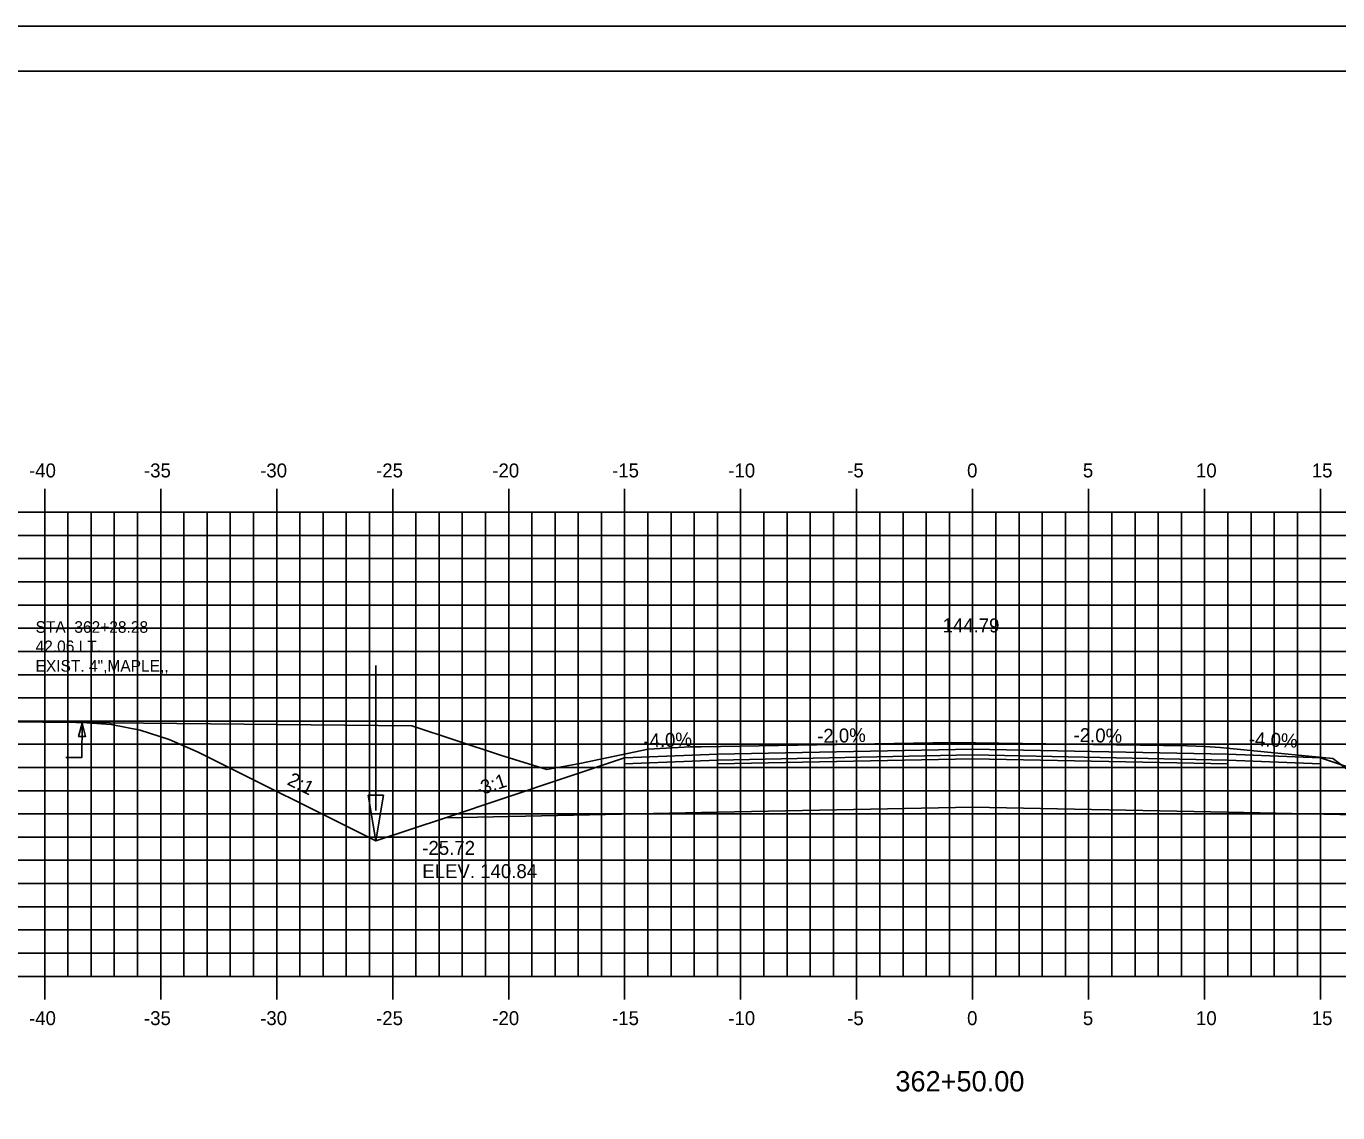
# Model space of a CAD drawing. Extents: x 1146746 to 1146916, y 608981 to 609091.
# Drawn here: x 1146788.6 to 1146845.2, y 609044.5 to 609091.3 of the extents above; entities that cross this region are included whole.
import ezdxf

# ---------------------------------------------------------------- set-up
doc = ezdxf.new("R2010")
doc.units = 0
for name, color, linetype in [('ANNOTATION', 7, 'Continuous'), ('BORDER', 7, 'Continuous'), ('D_Drainage_Ditch_Line', 7, 'Continuous'), ('D_Roadway_Centerline', 7, 'Continuous'), ('D_Roadway_Centerline_Text', 7, 'Continuous'), ('D_Roadway_Edge_Shoulder', 7, 'Continuous'), ('D_Roadway_Edge_TW', 7, 'Continuous'), ('D_Roadway_Pavement', 7, 'Continuous'), ('D_Roadway_SlopeLines', 7, 'Continuous'), ('D_Roadway_SubGrade', 7, 'Continuous'), ('D_Text_Monospaced', 7, 'Continuous'), ('D_Text_Standard', 7, 'Continuous'), ('H_V ANNOTATION', 7, 'Continuous'), ('MAJOR', 7, 'Continuous'), ('MINOR', 7, 'Continuous'), ('PLOT BOUNDARY', 7, 'Continuous'), ('S_Roadway_Centerline', 7, 'Continuous')]:
    doc.layers.add(name, color=color, linetype=linetype)

msp = doc.modelspace()

# ---------------------------------------------------------------- linework, layer by layer
msp.add_lwpolyline([(1146791.047, 609061.273), (1146792.297, 609061.185), (1146793.547, 609060.943), (1146794.797, 609060.547), (1146796.047, 609059.999), (1146803.703, 609056.171), (1146806.703, 609057.171), (1146814.427, 609059.745), (1146814.428, 609059.745), (1146818.428, 609059.905), (1146829.428, 609060.125), (1146840.428, 609059.905), (1146844.428, 609059.745), (1146852.151, 609057.171), (1146855.151, 609056.171), (1146862.242, 609059.716), (1146863.492, 609060.262), (1146864.742, 609060.648), (1146865.992, 609060.875), (1146867.242, 609060.943)])
at = {"layer": 'BORDER'}
msp.add_lwpolyline([(1146754.428, 608984.335), (1146914.428, 608984.335), (1146914.428, 609089.335), (1146754.428, 609089.335)], close=True, dxfattribs=at)
at = {"layer": 'D_Drainage_Ditch_Line'}
msp.add_line((1146803.703, 609057.483), (1146803.704, 609063.727), dxfattribs=at)
msp.add_lwpolyline([(1146803.375, 609058.139), (1146804.031, 609058.139), (1146803.703, 609056.171)], close=True, dxfattribs=at)
at = {"layer": 'D_Roadway_Edge_Shoulder'}
for points in [[(1146818.428, 609059.905), (1146814.428, 609059.745), (1146814.428, 609059.495), (1146818.428, 609059.655)], [(1146840.428, 609059.905), (1146844.428, 609059.745), (1146844.428, 609059.495), (1146840.428, 609059.655)]]:
    msp.add_lwpolyline(points, close=True, dxfattribs=at)
at = {"layer": 'D_Roadway_Edge_TW'}
msp.add_lwpolyline([(1146818.428, 609059.655), (1146818.428, 609059.905), (1146829.428, 609060.125), (1146840.428, 609059.905), (1146840.428, 609059.655), (1146829.428, 609059.875)], close=True, dxfattribs=at)
at = {"layer": 'D_Roadway_Pavement'}
msp.add_lwpolyline([(1146818.428, 609059.489), (1146818.428, 609059.655), (1146829.428, 609059.875), (1146840.428, 609059.655), (1146840.428, 609059.489), (1146829.428, 609059.709)], close=True, dxfattribs=at)
at = {"layer": 'D_Roadway_SlopeLines'}
for points in [[(1146803.703, 609056.171), (1146796.047, 609059.999), (1146794.797, 609060.547), (1146793.547, 609060.943), (1146792.297, 609061.185), (1146791.047, 609061.273)], [(1146806.703, 609057.171), (1146803.703, 609056.171)]]:
    msp.add_lwpolyline(points, dxfattribs=at)
at = {"layer": 'D_Roadway_SubGrade'}
for points in [[(1146818.428, 609059.489), (1146818.428, 609059.655), (1146814.428, 609059.495), (1146814.428, 609059.745), (1146814.427, 609059.745), (1146806.703, 609057.171), (1146818.428, 609057.405)], [(1146818.428, 609057.405), (1146818.428, 609059.489), (1146829.428, 609059.709), (1146840.428, 609059.489), (1146840.428, 609057.405), (1146829.428, 609057.625)], [(1146840.428, 609059.489), (1146840.428, 609059.655), (1146844.428, 609059.495), (1146844.428, 609059.745), (1146844.428, 609059.745), (1146852.151, 609057.171), (1146840.428, 609057.405)]]:
    msp.add_lwpolyline(points, close=True, dxfattribs=at)
at = {"layer": 'D_Text_Standard'}
msp.add_lwpolyline([(1146791.047, 609061.249), (1146791.023, 609059.762), (1146790.343, 609059.762)], dxfattribs=at)
msp.add_lwpolyline([(1146791.047, 609061.249), (1146791.183, 609060.665), (1146790.892, 609060.669)], close=True, dxfattribs=at)
at = {"layer": 'MAJOR'}
for p, q in [((1146789.428, 609071.337), (1146789.428, 609070.335)), ((1146794.428, 609071.337), (1146794.428, 609070.335)), ((1146799.428, 609071.337), (1146799.428, 609070.335)), ((1146804.428, 609071.337), (1146804.428, 609070.335)), ((1146809.428, 609071.337), (1146809.428, 609070.335)), ((1146814.428, 609071.337), (1146814.428, 609070.335)), ((1146819.428, 609071.337), (1146819.428, 609070.335)), ((1146824.428, 609071.337), (1146824.428, 609070.335)), ((1146829.428, 609071.337), (1146829.428, 609070.335)), ((1146834.428, 609071.337), (1146834.428, 609070.335)), ((1146839.428, 609071.337), (1146839.428, 609070.335)), ((1146844.428, 609071.337), (1146844.428, 609070.335)), ((1146759.428, 609070.335), (1146899.428, 609070.335)), ((1146759.428, 609070.335), (1146899.428, 609070.335)), ((1146789.428, 609050.335), (1146789.428, 609070.335)), ((1146794.428, 609050.335), (1146794.428, 609070.335)), ((1146799.428, 609050.335), (1146799.428, 609070.335)), ((1146804.428, 609050.335), (1146804.428, 609070.335)), ((1146809.428, 609050.335), (1146809.428, 609070.335)), ((1146814.428, 609050.335), (1146814.428, 609070.335)), ((1146819.428, 609050.335), (1146819.428, 609070.335)), ((1146824.428, 609050.335), (1146824.428, 609070.335)), ((1146829.428, 609050.335), (1146829.428, 609070.335)), ((1146834.428, 609050.335), (1146834.428, 609070.335)), ((1146839.428, 609050.335), (1146839.428, 609070.335)), ((1146844.428, 609050.335), (1146844.428, 609070.335)), ((1146759.428, 609065.335), (1146899.428, 609065.335)), ((1146759.428, 609060.335), (1146899.428, 609060.335)), ((1146759.428, 609055.335), (1146899.428, 609055.335)), ((1146759.428, 609050.335), (1146899.428, 609050.335)), ((1146759.428, 609050.335), (1146899.428, 609050.335)), ((1146789.428, 609049.333), (1146789.428, 609050.335)), ((1146794.428, 609049.333), (1146794.428, 609050.335)), ((1146799.428, 609049.333), (1146799.428, 609050.335)), ((1146804.428, 609049.333), (1146804.428, 609050.335)), ((1146809.428, 609049.333), (1146809.428, 609050.335)), ((1146814.428, 609049.333), (1146814.428, 609050.335)), ((1146819.428, 609049.333), (1146819.428, 609050.335)), ((1146824.428, 609049.333), (1146824.428, 609050.335)), ((1146829.428, 609049.333), (1146829.428, 609050.335)), ((1146834.428, 609049.333), (1146834.428, 609050.335)), ((1146839.428, 609049.333), (1146839.428, 609050.335)), ((1146844.428, 609049.333), (1146844.428, 609050.335))]:
    msp.add_line(p, q, dxfattribs=at)
at = {"layer": 'MINOR'}
for p, q in [((1146790.428, 609050.335), (1146790.428, 609070.335)), ((1146791.428, 609050.335), (1146791.428, 609070.335)), ((1146792.428, 609050.335), (1146792.428, 609070.335)), ((1146793.428, 609050.335), (1146793.428, 609070.335)), ((1146795.428, 609050.335), (1146795.428, 609070.335)), ((1146796.428, 609050.335), (1146796.428, 609070.335)), ((1146797.428, 609050.335), (1146797.428, 609070.335)), ((1146798.428, 609050.335), (1146798.428, 609070.335)), ((1146800.428, 609050.335), (1146800.428, 609070.335)), ((1146801.428, 609050.335), (1146801.428, 609070.335)), ((1146802.428, 609050.335), (1146802.428, 609070.335)), ((1146803.428, 609050.335), (1146803.428, 609070.335)), ((1146805.428, 609050.335), (1146805.428, 609070.335)), ((1146806.428, 609050.335), (1146806.428, 609070.335)), ((1146807.428, 609050.335), (1146807.428, 609070.335)), ((1146808.428, 609050.335), (1146808.428, 609070.335)), ((1146810.428, 609050.335), (1146810.428, 609070.335)), ((1146811.428, 609050.335), (1146811.428, 609070.335)), ((1146812.428, 609050.335), (1146812.428, 609070.335)), ((1146813.428, 609050.335), (1146813.428, 609070.335)), ((1146815.428, 609050.335), (1146815.428, 609070.335)), ((1146816.428, 609050.335), (1146816.428, 609070.335)), ((1146817.428, 609050.335), (1146817.428, 609070.335)), ((1146818.428, 609050.335), (1146818.428, 609070.335)), ((1146820.428, 609050.335), (1146820.428, 609070.335)), ((1146821.428, 609050.335), (1146821.428, 609070.335)), ((1146822.428, 609050.335), (1146822.428, 609070.335)), ((1146823.428, 609050.335), (1146823.428, 609070.335)), ((1146825.428, 609050.335), (1146825.428, 609070.335)), ((1146826.428, 609050.335), (1146826.428, 609070.335)), ((1146827.428, 609050.335), (1146827.428, 609070.335)), ((1146828.428, 609050.335), (1146828.428, 609070.335)), ((1146830.428, 609050.335), (1146830.428, 609070.335)), ((1146831.428, 609050.335), (1146831.428, 609070.335)), ((1146832.428, 609050.335), (1146832.428, 609070.335)), ((1146833.428, 609050.335), (1146833.428, 609070.335)), ((1146835.428, 609050.335), (1146835.428, 609070.335)), ((1146836.428, 609050.335), (1146836.428, 609070.335)), ((1146837.428, 609050.335), (1146837.428, 609070.335)), ((1146838.428, 609050.335), (1146838.428, 609070.335)), ((1146840.428, 609050.335), (1146840.428, 609070.335)), ((1146841.428, 609050.335), (1146841.428, 609070.335)), ((1146842.428, 609050.335), (1146842.428, 609070.335)), ((1146843.428, 609050.335), (1146843.428, 609070.335)), ((1146759.428, 609069.335), (1146899.428, 609069.335)), ((1146759.428, 609068.335), (1146899.428, 609068.335)), ((1146759.428, 609067.335), (1146899.428, 609067.335)), ((1146759.428, 609066.335), (1146899.428, 609066.335)), ((1146759.428, 609064.335), (1146899.428, 609064.335)), ((1146759.428, 609063.335), (1146899.428, 609063.335)), ((1146759.428, 609062.335), (1146899.428, 609062.335)), ((1146759.428, 609061.335), (1146899.428, 609061.335)), ((1146759.428, 609059.335), (1146899.428, 609059.335)), ((1146759.428, 609058.335), (1146899.428, 609058.335)), ((1146759.428, 609057.335), (1146899.428, 609057.335)), ((1146759.428, 609056.335), (1146899.428, 609056.335)), ((1146759.428, 609054.335), (1146899.428, 609054.335)), ((1146759.428, 609053.335), (1146899.428, 609053.335)), ((1146759.428, 609052.335), (1146899.428, 609052.335)), ((1146759.428, 609051.335), (1146899.428, 609051.335))]:
    msp.add_line(p, q, dxfattribs=at)
at = {"layer": 'PLOT BOUNDARY'}
msp.add_lwpolyline([(1146746.335, 608981.276), (1146916.335, 608981.276), (1146916.335, 609091.276), (1146746.335, 609091.276)], close=True, dxfattribs=at)
at = {"layer": 'S_Roadway_Centerline'}
msp.add_lwpolyline([(1146779.336, 609061.362), (1146783.547, 609061.347), (1146805.256, 609061.134), (1146809.082, 609059.861), (1146811.069, 609059.254), (1146812.495, 609059.513), (1146815.447, 609060.131), (1146817.252, 609060.222), (1146817.72, 609060.231), (1146827.705, 609060.397), (1146828.534, 609060.409), (1146838.673, 609060.265), (1146839.449, 609060.245), (1146840.103, 609060.192), (1146841.398, 609060.074), (1146844.953, 609059.719), (1146845.827, 609059.059), (1146847.055, 609058.398), (1146848.196, 609058.671), (1146848.525, 609058.74), (1146851.732, 609059.665), (1146855.862, 609060.73), (1146861.215, 609060.999), (1146871.652, 609060.902)], dxfattribs=at)

# ---------------------------------------------------------------- texts
at = {"layer": 'ANNOTATION'}
for s, rotation, p in [('-4.0%', 2.2906, (1146815.244, 609060.179)), ('-2.0%', 1.1458, (1146822.731, 609060.392)), ('-2.0%', 358.8542, (1146833.771, 609060.439)), ('-4.0%', 357.7094, (1146841.324, 609060.27)), ('2:1', 333.4349, (1146799.842, 609058.619)), ('-3:1', 18.4348, (1146808.082, 609058.085))]:
    msp.add_text(s, height=0.6, rotation=rotation, dxfattribs=at).set_placement(p)
at = {"layer": 'D_Roadway_Centerline'}
for s, p in [('C', (1146829.423, 609060.125)), ('L', (1146829.428, 609060.118))]:
    msp.add_text(s, height=0.0146, dxfattribs=at).set_placement(p)
at = {"layer": 'D_Roadway_Centerline_Text'}
msp.add_text('144.79', height=0.6, dxfattribs=at).set_placement((1146828.128, 609065.157))
at = {"layer": 'D_Text_Monospaced'}
for s, height, p in [('STA. 362+28.28', 0.49998, (1146789.035, 609065.139)), ('42.06 LT.', 0.5, (1146789.035, 609064.305)), ('EXIST. 4",MAPLE,,', 0.49998, (1146789.035, 609063.465))]:
    msp.add_text(s, height=height, dxfattribs=at).set_placement(p)
at = {"layer": 'D_Text_Standard'}
for s, p in [('-25.72', (1146805.703, 609055.571)), ('ELEV. 140.84', (1146805.703, 609054.569))]:
    msp.add_text(s, height=0.6, dxfattribs=at).set_placement(p)
at = {"layer": 'H_V ANNOTATION'}
for s, height, p in [('-40', 0.6, (1146788.753, 609071.835)), ('-35', 0.6, (1146793.708, 609071.835)), ('-30', 0.6, (1146798.716, 609071.835)), ('-25', 0.6, (1146803.713, 609071.835)), ('-20', 0.6, (1146808.721, 609071.835)), ('-15', 0.6, (1146813.885, 609071.835)), ('-10', 0.6, (1146818.893, 609071.835)), ('-5', 0.6, (1146824.018, 609071.835)), ('0', 0.6, (1146829.187, 609071.835)), ('5', 0.6, (1146834.179, 609071.835)), ('10', 0.6, (1146839.053, 609071.835)), ('15', 0.6, (1146844.045, 609071.835)), ('-40', 0.6, (1146788.753, 609048.235)), ('-35', 0.6, (1146793.708, 609048.235)), ('-30', 0.6, (1146798.716, 609048.235)), ('-25', 0.6, (1146803.713, 609048.235)), ('-20', 0.6, (1146808.721, 609048.235)), ('-15', 0.6, (1146813.885, 609048.235)), ('-10', 0.6, (1146818.893, 609048.235)), ('-5', 0.6, (1146824.018, 609048.235)), ('0', 0.6, (1146829.187, 609048.235)), ('5', 0.6, (1146834.179, 609048.235)), ('10', 0.6, (1146839.053, 609048.235)), ('15', 0.6, (1146844.045, 609048.235)), ('362+50.00', 0.875, (1146826.096, 609045.378))]:
    msp.add_text(s, height=height, dxfattribs=at).set_placement(p)
at = {"layer": 'S_Roadway_Centerline'}
for s, p in [('L', (1146828.526, 609060.401)), ('C', (1146828.529, 609060.409))]:
    msp.add_text(s, height=0.0146, dxfattribs=at).set_placement(p)

doc.saveas('drawing.dxf')
